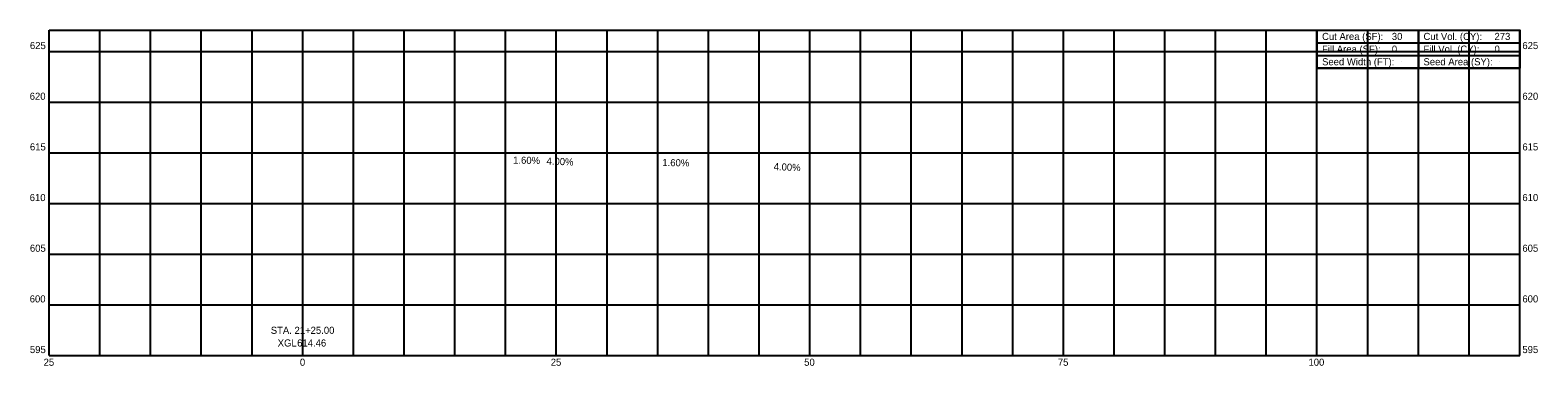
# Model space of a CAD drawing. Extents: x -27 to 122, y 594 to 627.
import ezdxf

# ---------------------------------------------------------------- set-up
doc = ezdxf.new("R2010")
doc.units = 0
for name, color, linetype in [('Default', 7, 'Continuous'), ('SH_Data', 7, 'Continuous'), ('SH_Major_Grid_Line', 7, 'Continuous'), ('SH_Masking', 7, 'Continuous'), ('SH_Text', 7, 'Continuous')]:
    doc.layers.add(name, color=color, linetype=linetype)

msp = doc.modelspace()

# ---------------------------------------------------------------- linework, layer by layer
at = {"layer": 'Default'}
msp.add_circle((120, 627.12), 0.000417, dxfattribs=at)
msp.add_circle((120, 627.12), 0.000417, dxfattribs=at)
msp.add_circle((120, 627.12), 0.000417, dxfattribs=at)
msp.add_circle((120, 627.12), 0.000417, dxfattribs=at)
msp.add_circle((120, 627.12), 0.000417, dxfattribs=at)
msp.add_circle((120, 627.12), 0.000417, dxfattribs=at)
msp.add_circle((120, 627.12), 0.000417, dxfattribs=at)
msp.add_circle((120, 627.12), 0.000417, dxfattribs=at)
msp.add_circle((120, 627.12), 0.000417, dxfattribs=at)
msp.add_circle((120, 627.12), 0.000417, dxfattribs=at)
msp.add_circle((120, 627.12), 0.000417, dxfattribs=at)
msp.add_circle((120, 627.12), 0.000417, dxfattribs=at)
at = {"layer": 'SH_Data'}
for p, q in [((100, 627.12), (120, 627.12)), ((100, 627.12), (100, 624.62)), ((100, 625.87), (120, 625.87)), ((110, 627.12), (110, 623.37)), ((120, 627.12), (120, 624.62)), ((100, 624.62), (120, 624.62)), ((108.3, 624), (108.3, 624)), ((117.95, 624), (117.95, 624))]:
    msp.add_line(p, q, dxfattribs=at)
msp.add_lwpolyline([(100, 624.62), (100, 623.37), (120, 623.37), (120, 624.62)], dxfattribs=at)
at = {"layer": 'SH_Major_Grid_Line'}
for p, q in [((-25, 627.12), (120, 627.12)), ((-25, 595), (-25, 627.12)), ((-20, 595), (-20, 627.12)), ((-15, 595), (-15, 627.12)), ((-10, 595), (-10, 627.12)), ((-5, 595), (-5, 627.12)), ((0, 595), (0, 627.12)), ((5, 595), (5, 627.12)), ((10, 595), (10, 627.12)), ((15, 595), (15, 627.12)), ((20, 595), (20, 627.12)), ((25, 595), (25, 627.12)), ((30, 595), (30, 627.12)), ((35, 595), (35, 627.12)), ((40, 595), (40, 627.12)), ((45, 595), (45, 627.12)), ((50, 595), (50, 627.12)), ((55, 595), (55, 627.12)), ((60, 595), (60, 627.12)), ((65, 595), (65, 627.12)), ((70, 595), (70, 627.12)), ((75, 595), (75, 627.12)), ((80, 595), (80, 627.12)), ((85, 595), (85, 627.12)), ((90, 595), (90, 627.12)), ((95, 595), (95, 627.12)), ((100, 595), (100, 627.12)), ((105, 595), (105, 627.12)), ((110, 595), (110, 627.12)), ((115, 595), (115, 627.12)), ((120, 595), (120, 627.12)), ((-25, 625), (120, 625)), ((-25, 620), (120, 620)), ((-25, 615), (120, 615)), ((-25, 610), (120, 610)), ((-25, 605), (120, 605)), ((-25, 600), (120, 600)), ((-25, 595), (120, 595))]:
    msp.add_line(p, q, dxfattribs=at)
at = {"layer": 'SH_Masking'}
msp.add_lwpolyline([(100, 627.12), (120, 627.12), (120, 623.37), (100, 623.37)], close=True, dxfattribs=at)

# ---------------------------------------------------------------- texts
at = {"layer": 'SH_Text'}
for s, p in [('625', (-26.9, 625.25)), ('Cut Area (SF):', (100.5, 626.15)), ('30', (107.38, 626.15)), ('Cut Vol. (CY):', (110.5, 626.15)), ('273', (117.5, 626.15)), ('625', (120.25, 625.25)), ('Seed Width (FT):', (100.5, 623.65)), ('Fill Area (SF):', (100.5, 624.9)), ('0', (107.38, 624.9)), ('Seed Area (SY):', (110.5, 623.65)), ('Fill Vol. (CY):', (110.5, 624.9)), ('0', (117.5, 624.9)), ('620', (-26.92, 620.25)), ('620', (120.25, 620.25)), ('615', (-26.9, 615.25)), ('615', (120.25, 615.25)), ('610', (-26.92, 610.25)), ('610', (120.25, 610.25)), ('605', (-26.9, 605.25)), ('605', (120.25, 605.25)), ('600', (-26.92, 600.25)), ('600', (120.25, 600.25)), ('STA. 21+25.00', (-3.15, 597.15)), ('XGL ', (-2.47, 595.9)), ('614.46', (-0.55, 595.9)), ('595', (-26.9, 595.25)), ('25', (-25.55, 594)), ('0', (-0.28, 594)), ('25', (24.45, 594)), ('50', (49.44, 594)), ('75', (74.45, 594)), ('100', (99.16, 594)), ('595', (120.25, 595.25))]:
    msp.add_text(s, height=0.7, dxfattribs=at).set_placement(p)
for s, rotation, p in [('1.60%', 359.0833, (20.74, 613.95)), ('4.00%', 357.7094, (24.03, 613.86)), ('1.60%', 359.0833, (35.45, 613.71)), ('4.00%', 357.7094, (46.42, 613.31))]:
    msp.add_text(s, height=0.7, rotation=rotation, dxfattribs=at).set_placement(p)

doc.saveas('drawing.dxf')
